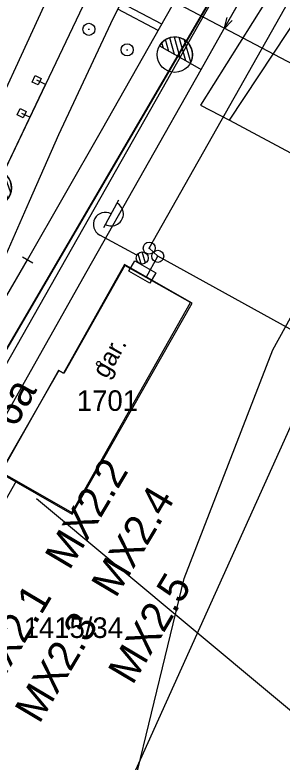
# Model space of a CAD drawing. Extents: x -781083 to -763634, y -1029516 to -1022695.
# Drawn here: x -765211.5 to -765189.4, y -1024336.1 to -1024274.3 of the extents above; entities that cross this region are included whole.
import ezdxf

# ---------------------------------------------------------------- set-up
doc = ezdxf.new("R2010")
doc.units = 0
for name, color, linetype in [('Default', 7, 'Continuous'), ('Hranice parcel', 7, 'Continuous'), ('Parcelní čísla', 7, 'Continuous'), ('PS120111-MOK', 7, 'Continuous'), ('PS_12-01-10_Kabelizace_nove_kabelizace', 7, 'Continuous'), ('SO128401_EOV_popisky', 7, 'Continuous'), ('SO128401_EOV_prvky', 7, 'Continuous'), ('SO128401_EOV_trasa', 7, 'Continuous'), ('Vrstva 1', 7, 'Continuous'), ('Vrstva 16', 7, 'Continuous'), ('Vrstva 2', 7, 'Continuous'), ('Vrstva 23', 7, 'Continuous'), ('Vrstva 25', 7, 'Continuous'), ('Vrstva 5', 7, 'Continuous'), ('Vrstva 50', 7, 'Continuous'), ('Vrstva 51', 7, 'Continuous'), ('Vrstva 7', 7, 'Continuous'), ('Značky bodu BP', 7, 'Continuous'), ('Značky budov', 7, 'Continuous'), ('ČD Telematika_TK', 7, 'Continuous')]:
    doc.layers.add(name, color=color, linetype=linetype)

# ---------------------------------------------------------------- blocks, each defined once
blk = doc.blocks.new('4.02')
at = {"layer": 'Značky budov'}
blk.add_circle((-0.07, 0.01), 1.75, dxfattribs=at)
blk = doc.blocks.new('1.05')
at = {"layer": 'Značky bodu BP'}
for radius in [5, 0.303]:
    blk.add_circle((0, 0), radius, dxfattribs=at)
blk = doc.blocks.new('C669_23')
at = {"layer": 'Vrstva 25'}
for p, q in [((0, 5), (0, 40)), ((7, 40), (33.01, 40)), ((-4.78, -1.45), (1.44, 4.76)), ((-2.39, -4.36), (4.38, 2.4))]:
    blk.add_line(p, q, dxfattribs=at)
blk.add_circle((0, 0), 5, dxfattribs=at)
blk.add_circle((0, 0), 5, dxfattribs=at)
for centre, start, end in [((10, 40), 359.99982, 179.99982), ((20, 39.88), 179.29725, 0.7024)]:
    blk.add_arc(centre, 10, start, end, dxfattribs=at)
blk = doc.blocks.new('C202')
at = {"layer": 'Vrstva 25'}
blk.add_lwpolyline([(-10, -5), (-10, 5), (10, 5), (10, -5), (-10, -5)], dxfattribs=at)
blk = doc.blocks.new('C053_4')
at = {"layer": 'Vrstva 50'}
blk.add_line((-0.5, 0), (0.5, 0), dxfattribs=at)
blk.add_circle((0, 0), 5, dxfattribs=at)
blk = doc.blocks.new('C084_2')
at = {"layer": 'Vrstva 2'}
blk.add_line((0, 5), (0, -5), dxfattribs=at)
blk = doc.blocks.new('C321')
at = {"layer": 'Vrstva 2'}
blk.add_lwpolyline([(9.66, 2.59), (0, 0), (9.66, -2.59)], dxfattribs=at)
blk = doc.blocks.new('C515_3')
at = {"layer": 'Vrstva 2'}
for p, q in [((-0.02, 35.76), (3.35, 39.13)), ((-0.02, 30.45), (7.16, 37.63)), ((-0.03, 19.84), (12.53, 32.4)), ((-0.02, 25.15), (10.19, 35.36)), ((-0.03, 14.54), (14.1, 28.67)), ((1.1, 10.37), (14.53, 23.79)), ((0, 10.29), (0, 0))]:
    blk.add_line(p, q, dxfattribs=at)
blk.add_lwpolyline([(0, 39.56), (0, 10.29)], dxfattribs=at)
blk.add_circle((0, 24.92), 14.64, dxfattribs=at)
blk.add_arc((0, 24.92), 14.63, 270.01913, 89.97998, dxfattribs=at)
blk = doc.blocks.new('C531')
at = {"layer": 'Vrstva 2'}
for p, q in [((0, 0), (0, -10)), ((-14.55, -28.49), (-11.05, -25)), ((-12.93, -32.53), (-5.4, -25)), ((-10.45, -35.71), (0.26, -25)), ((-7.2, -38.12), (5.92, -25)), ((-3.07, -39.65), (11.57, -25)), ((2.45, -39.78), (14.76, -27.47))]:
    blk.add_line(p, q, dxfattribs=at)
blk.add_lwpolyline([(15, -25), (-15, -25)], dxfattribs=at)
blk.add_circle((0, -25), 15, dxfattribs=at)
blk.add_arc((0, -25), 15, 179.99649, 359.99649, dxfattribs=at)
blk = doc.blocks.new('POINT_DISPLAY')
at = {"layer": 'Default'}
blk.add_line((0, 0), (0, 0), dxfattribs=at)
blk = doc.blocks.new('C335')
at = {"layer": 'Vrstva 7'}
blk.add_blockref('POINT_DISPLAY', (0, 0), dxfattribs=at)

msp = doc.modelspace()

# ---------------------------------------------------------------- linework, layer by layer
at = {"layer": 'Hranice parcel'}
for p, q in [((-765200.62, -1024296.03), (-765199.67, -1024294.27)), ((-765185.57, -1024302.05), (-765199.67, -1024294.27)), ((-765227.39, -1024341.18), (-765211.36, -1024312.85))]:
    msp.add_line(p, q, dxfattribs=at)
for points in [[(-765199.67, -1024294.27), (-765200.37, -1024293.59), (-765169.79, -1024239.44), (-765167.98, -1024240.28)], [(-765200.62, -1024296.03), (-765202.38, -1024295.03), (-765207.43, -1024303.97), (-765207.87, -1024303.72), (-765212.62, -1024312.13), (-765211.36, -1024312.85)], [(-765211.36, -1024312.85), (-765206.77, -1024315.46), (-765196.95, -1024298.1), (-765200.62, -1024296.03)], [(-765185.57, -1024302.05), (-765187.45, -1024305.59), (-765201.77, -1024337.33), (-765206.13, -1024339.71), (-765227.39, -1024341.18)]]:
    msp.add_lwpolyline(points, dxfattribs=at)
at = {"layer": 'PS120111-MOK'}
msp.add_lwpolyline([(-765225.805, -1024328.474), (-765227.041, -1024327.403), (-765189.607, -1024263.284), (-765167.089, -1024223.521), (-765111.836, -1024124.939), (-765108.851, -1024119.501), (-765085.73, -1024077.899), (-765081.023, -1024080.523), (-765060.822, -1024044.042), (-765057.835, -1024038.647), (-765021.888, -1023965.037), (-765009.529, -1023945.01), (-764990.029, -1023909.994), (-764973.93, -1023884.565), (-764957.796, -1023847.878), (-764953.349, -1023837.037), (-764952.504, -1023834.976), (-764951.393, -1023835.06)], dxfattribs=at)
at = {"layer": 'PS_12-01-10_Kabelizace_nove_kabelizace'}
msp.add_line((-765229.311, -1024331.29), (-765189.607, -1024263.284), dxfattribs=at)
msp.add_lwpolyline([(-765213.127, -1024288.831), (-765205.558, -1024272.944), (-765197.867, -1024258.547), (-765198.078, -1024258.43)], dxfattribs=at)
at = {"layer": 'SO128401_EOV_prvky'}
for points in [[(-765209.303, -1024279.558), (-765209.546, -1024280.085), (-765210.054, -1024279.851), (-765209.811, -1024279.324)], [(-765210.55, -1024282.276), (-765210.793, -1024282.803), (-765211.301, -1024282.569), (-765211.058, -1024282.042)]]:
    msp.add_lwpolyline(points, close=True, dxfattribs=at)
at = {"layer": 'SO128401_EOV_trasa'}
msp.add_line((-765210.925, -1024282.422), (-765210.222, -1024282.746), dxfattribs=at)
for points in [[(-765111.624, -1024019.292), (-765109.87, -1024016.203), (-765060.824, -1024044.045), (-765060.824, -1024044.045), (-765081.023, -1024080.523), (-765081.023, -1024080.523), (-765085.73, -1024077.899), (-765108.851, -1024119.501), (-765111.836, -1024124.939), (-765167.089, -1024223.521), (-765176.711, -1024240.445), (-765189.607, -1024263.284), (-765189.607, -1024263.284), (-765225.916, -1024325.475), (-765224.46, -1024326.168)], [(-765225.916, -1024325.475), (-765230.049, -1024323.516), (-765229.11, -1024321.947), (-765213.127, -1024288.831), (-765208.946, -1024280.054), (-765208.946, -1024280.054), (-765209.679, -1024279.705)]]:
    msp.add_lwpolyline(points, dxfattribs=at)
at = {"layer": 'Vrstva 1'}
for points in [[(-765215.522, -1024287.533), (-765214.869, -1024286.147), (-765208.592, -1024272.488), (-765202.041, -1024257.278), (-765199.225, -1024250.55), (-765195.719, -1024242.277), (-765191.973, -1024234.063), (-765191.905, -1024233.922), (-765187.773, -1024225.954), (-765183.261, -1024217.887), (-765177.292, -1024207.279), (-765170.878, -1024195.834), (-765163.532, -1024182.764), (-765155.727, -1024168.863), (-765148.415, -1024155.812), (-765140.866, -1024142.346)], [(-765227.172, -1024323.332), (-765226.383, -1024321.987), (-765218.823, -1024308.994), (-765212.016, -1024293.682), (-765210.286, -1024289.72), (-765207.837, -1024284.198), (-765203.542, -1024274.997), (-765199.177, -1024266.185), (-765195.745, -1024259.62), (-765191.959, -1024252.744), (-765183.924, -1024238.408), (-765177.594, -1024227.134), (-765171.735, -1024216.696), (-765164.143, -1024203.205), (-765156.397, -1024189.358), (-765149.423, -1024176.961), (-765143.434, -1024166.31), (-765138.578, -1024157.675), (-765133.719, -1024149)], [(-765196.085, -1024278.806), (-765194.209, -1024275.468), (-765190.323, -1024268.633), (-765181.566, -1024253.231), (-765176.626, -1024244.51), (-765168.111, -1024229.414), (-765158.27, -1024211.855), (-765152.182, -1024200.956), (-765148.92, -1024195.244), (-765140.746, -1024180.761), (-765133.358, -1024167.67), (-765132.595, -1024166.323)], [(-765227.172, -1024323.332), (-765226.383, -1024321.987), (-765218.823, -1024308.994), (-765210.425, -1024294.562), (-765204.319, -1024283.867), (-765196.481, -1024270.015), (-765194.577, -1024266.628), (-765187.356, -1024253.776), (-765179.867, -1024240.503), (-765173.904, -1024229.916)], [(-765221.676, -1024324.07), (-765221.602, -1024323.932), (-765215.053, -1024312.39), (-765205.493, -1024295.484), (-765196.085, -1024278.806)]]:
    msp.add_lwpolyline(points, dxfattribs=at)
at = {"layer": 'Vrstva 16'}
for points in [[(-765196.139, -1024281.778), (-765193.738, -1024283.002), (-765180.473, -1024262.935), (-765183.248, -1024261.22), (-765196.139, -1024281.778)], [(-765193.738, -1024283.002), (-765182.878, -1024288.822)]]:
    msp.add_lwpolyline(points, dxfattribs=at)
at = {"layer": 'Vrstva 2'}
for p, q in [((-765194.209, -1024275.468), (-765190.323, -1024268.633)), ((-765196.085, -1024278.806), (-765194.209, -1024275.468))]:
    msp.add_line(p, q, dxfattribs=at)
for points in [[(-765215.522, -1024287.533), (-765214.869, -1024286.147), (-765208.592, -1024272.488), (-765202.041, -1024257.278)], [(-765227.172, -1024323.332), (-765226.383, -1024321.987), (-765218.823, -1024308.994), (-765210.425, -1024294.562)]]:
    msp.add_lwpolyline(points, dxfattribs=at)
at = {"layer": 'Vrstva 23'}
msp.add_lwpolyline([(-765212.716, -1024312.175), (-765206.749, -1024315.61), (-765196.836, -1024298.138), (-765202.409, -1024294.95), (-765207.461, -1024303.942), (-765207.86, -1024303.73), (-765212.716, -1024312.175)], dxfattribs=at)
at = {"layer": 'Vrstva 25'}
msp.add_lwpolyline([(-765183.627, -1024336.105), (-765209.691, -1024314.336)], dxfattribs=at)
at = {"layer": 'Vrstva 5'}
msp.add_line((-765204.077, -1024270.142), (-765137.727, -1024305.261), dxfattribs=at)
at = {"layer": 'Vrstva 51'}
msp.add_lwpolyline([(-765237.237, -1024342.164), (-765229.818, -1024342.411), (-765204.257, -1024340.379), (-765202.415, -1024339.482), (-765201.543, -1024337.639), (-765197.493, -1024320.94), (-765190.15, -1024301.998), (-765182.878, -1024288.822)], dxfattribs=at)
at = {"layer": 'Vrstva 7'}
for p, q in [((-765199.341, -1024275.07), (-765202.697, -1024273.291)), ((-765199.637, -1024275.592), (-765202.964, -1024273.829))]:
    msp.add_line(p, q, dxfattribs=at)
at = {"layer": 'ČD Telematika_TK'}
msp.add_lwpolyline([(-765257.028, -1024404.569), (-765256.037, -1024398.213), (-765249.421, -1024374.188), (-765226.425, -1024328.292), (-765185.224, -1024255.545), (-765167.149, -1024223.486), (-765171.928, -1024220.746), (-765141.483, -1024166.52), (-765136.718, -1024169.454), (-765086.954, -1024080.425), (-765063.726, -1024094.284), (-765054.277, -1024080.444), (-765052.94, -1024078.307), (-765049.809, -1024079.983), (-765033.351, -1024048.633), (-765033.134, -1024014.623), (-765034.915, -1024000.619), (-765019.65, -1023968.646), (-765007.996, -1023946.352)], dxfattribs=at)

# ---------------------------------------------------------------- block references
at = {"layer": 'Vrstva 2'}
for name, p, xscale, yscale, rotation in [('C321', (-765194.209, -1024275.468), 0.1, 0.10000000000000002, 60.379305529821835), ('C515_3', (-765196.085, -1024278.806), 0.09999999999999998, 0.09999999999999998, 60.66343933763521), ('C531', (-765215.522, -1024287.533), 0.09999999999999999, 0.10000000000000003, 64.57068549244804), ('C084_2', (-765210.425, -1024294.562), 0.09999999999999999, 0.09999999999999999, 59.80433341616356)]:
    msp.add_blockref(name, p, dxfattribs=dict(at, xscale=xscale, yscale=yscale, rotation=rotation))
at = {"layer": 'Vrstva 25'}
for name, p, xscale, yscale, rotation in [('C669_23', (-765200.951, -1024294.412), 0.1, 0.09999999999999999, 61.60492305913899), ('C202', (-765200.953, -1024295.564), 0.09999999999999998, 0.09999999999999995, 150.22861114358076)]:
    msp.add_blockref(name, p, dxfattribs=dict(at, xscale=xscale, yscale=yscale, rotation=rotation))
at = {"layer": 'Vrstva 50', "xscale": 0.1, "yscale": 0.10000000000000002}
for p in [(-765205.36, -1024275.49), (-765202.194, -1024277.189)]:
    msp.add_blockref('C053_4', p, dxfattribs=at)
at = {"layer": 'Vrstva 7', "xscale": 0.10000000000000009, "yscale": 0.10000000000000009, "rotation": 90}
msp.add_blockref('C335', (-765201.28, -1024274.382), dxfattribs=at)
at = {"layer": 'Značky bodu BP', "xscale": 0.1, "yscale": 0.10000000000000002}
for p in [(-765200.37, -1024293.59), (-765199.67, -1024294.27)]:
    msp.add_blockref('1.05', p, dxfattribs=at)
at = {"layer": 'Značky budov', "xscale": 0.1, "yscale": 0.10000000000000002}
msp.add_blockref('4.02', (-765204.55, -1024303.15), dxfattribs=at)

# ---------------------------------------------------------------- texts
at = {"layer": 'Parcelní čísla'}
for s, p in [('1701', (-765206.36, -1024307.06)), ('1415/34', (-765210.76, -1024325.85))]:
    msp.add_text(s, height=1.7, dxfattribs=at).set_placement(p)
at = {"layer": 'SO128401_EOV_popisky'}
for s, p in [('MX2.2', (-765206.977, -1024320.326)), ('MX2.4', (-765203.144, -1024322.627)), ('MX2.5', (-765201.757, -1024329.818)), ('MX2.1', (-765213.3, -1024330.729)), ('MX2.3', (-765209.467, -1024333.03))]:
    msp.add_text(s, height=2.5, rotation=59.25687, dxfattribs=at).set_placement(p)
at = {"layer": 'Vrstva 1'}
msp.add_text('6a', height=2.5, rotation=60.51272, dxfattribs=at).set_placement((-765211.446, -1024308.55))
at = {"layer": 'Vrstva 23'}
msp.add_text('gar.', height=1.5, rotation=60.43094, dxfattribs=at).set_placement((-765203.879, -1024304.468))

doc.saveas('drawing.dxf')
